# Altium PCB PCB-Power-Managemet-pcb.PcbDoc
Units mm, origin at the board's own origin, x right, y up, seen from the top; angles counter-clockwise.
Board outline 99.48 x 99.65 mm, 2 copper layers (Top Layer, Bottom Layer), stack 1.41 mm thick; 27 components, 20 nets, 70 pads, 5 vias.
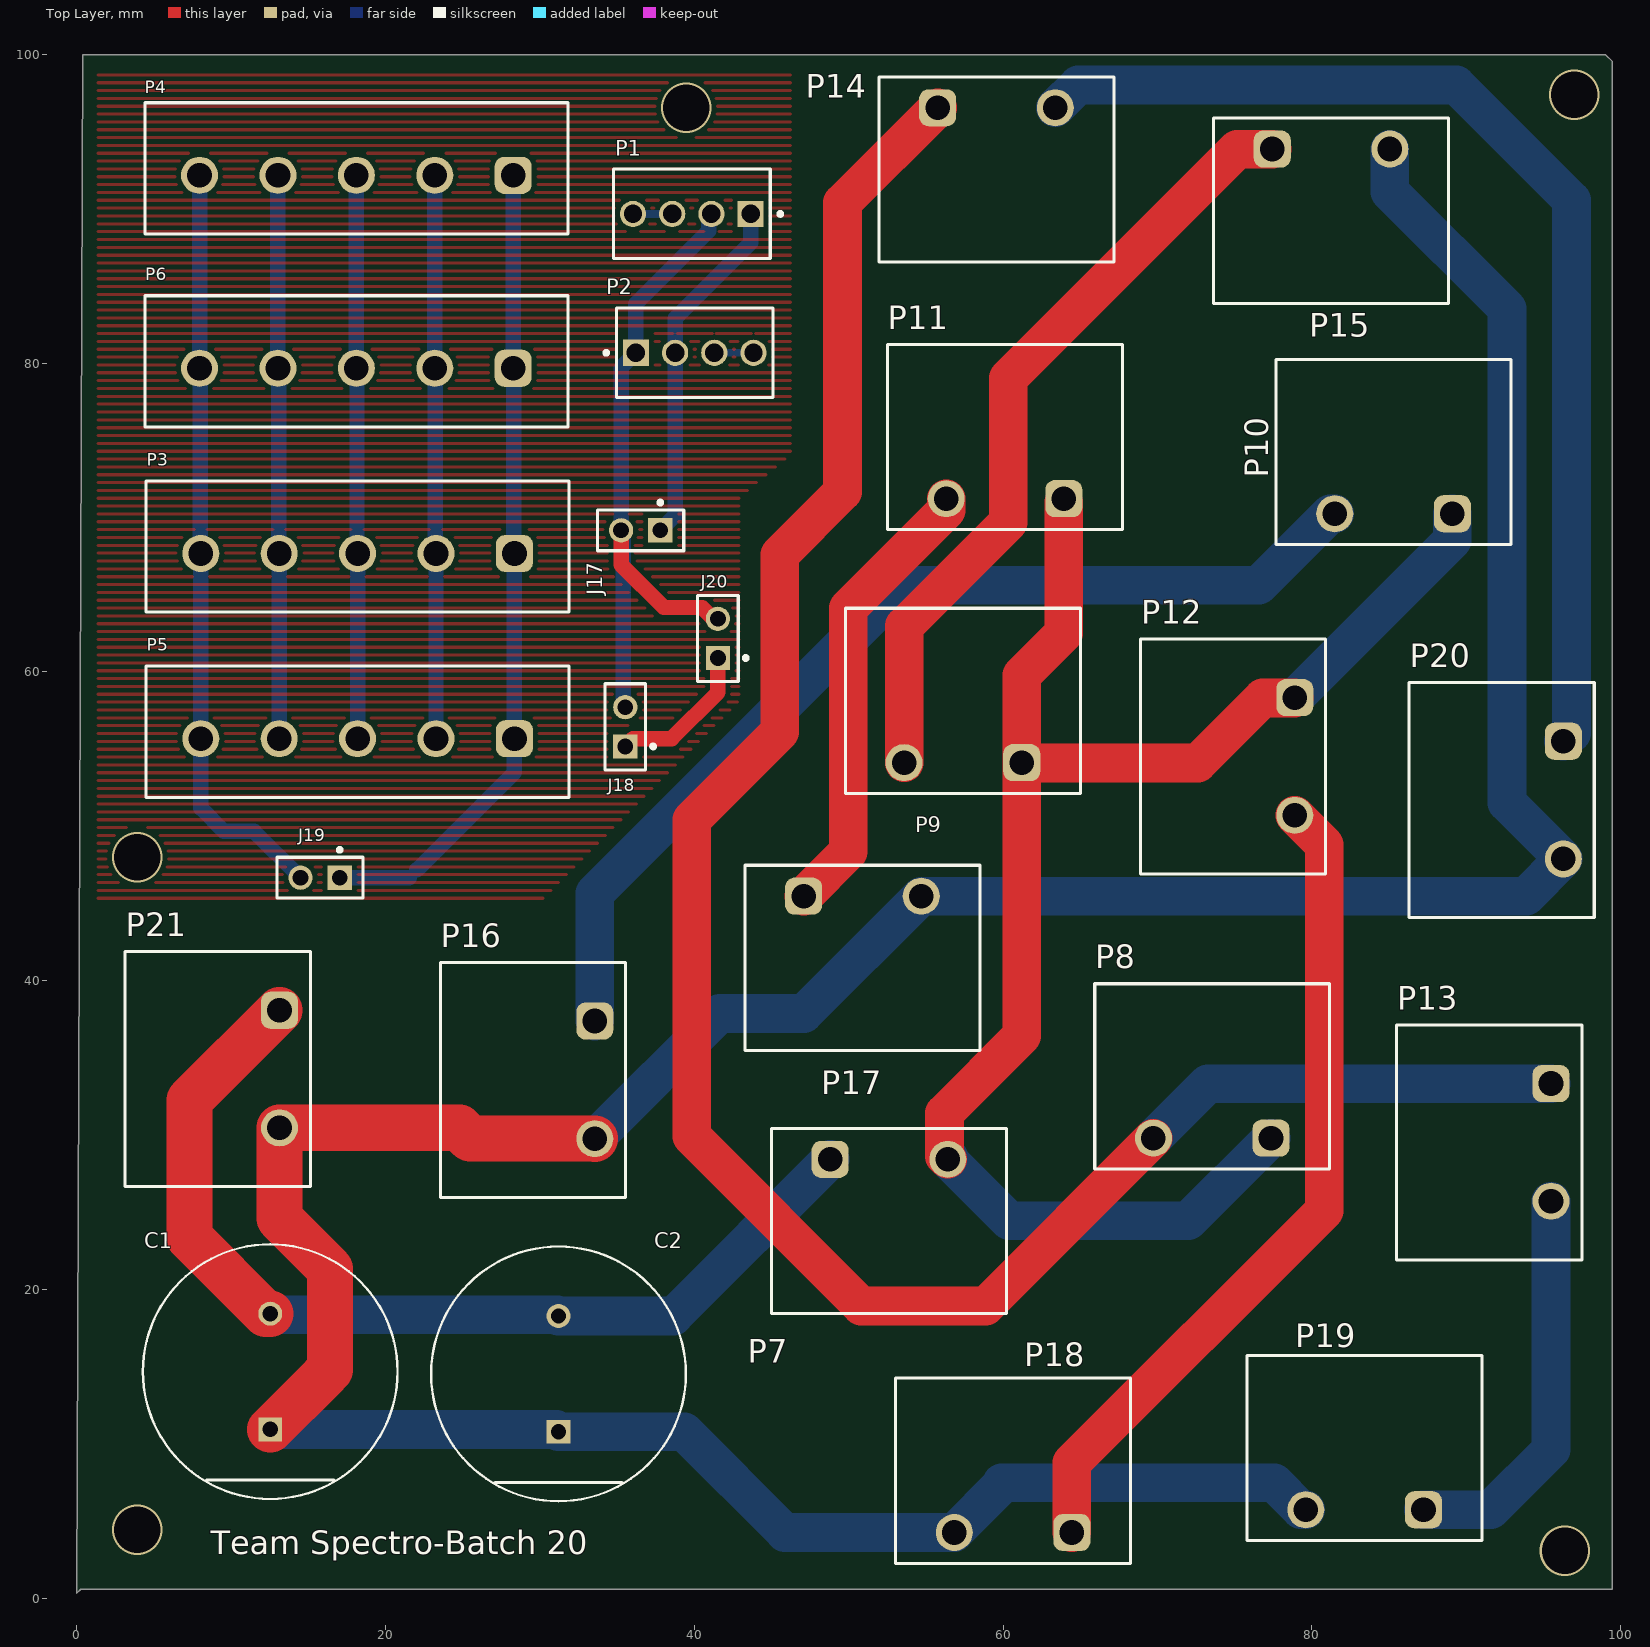
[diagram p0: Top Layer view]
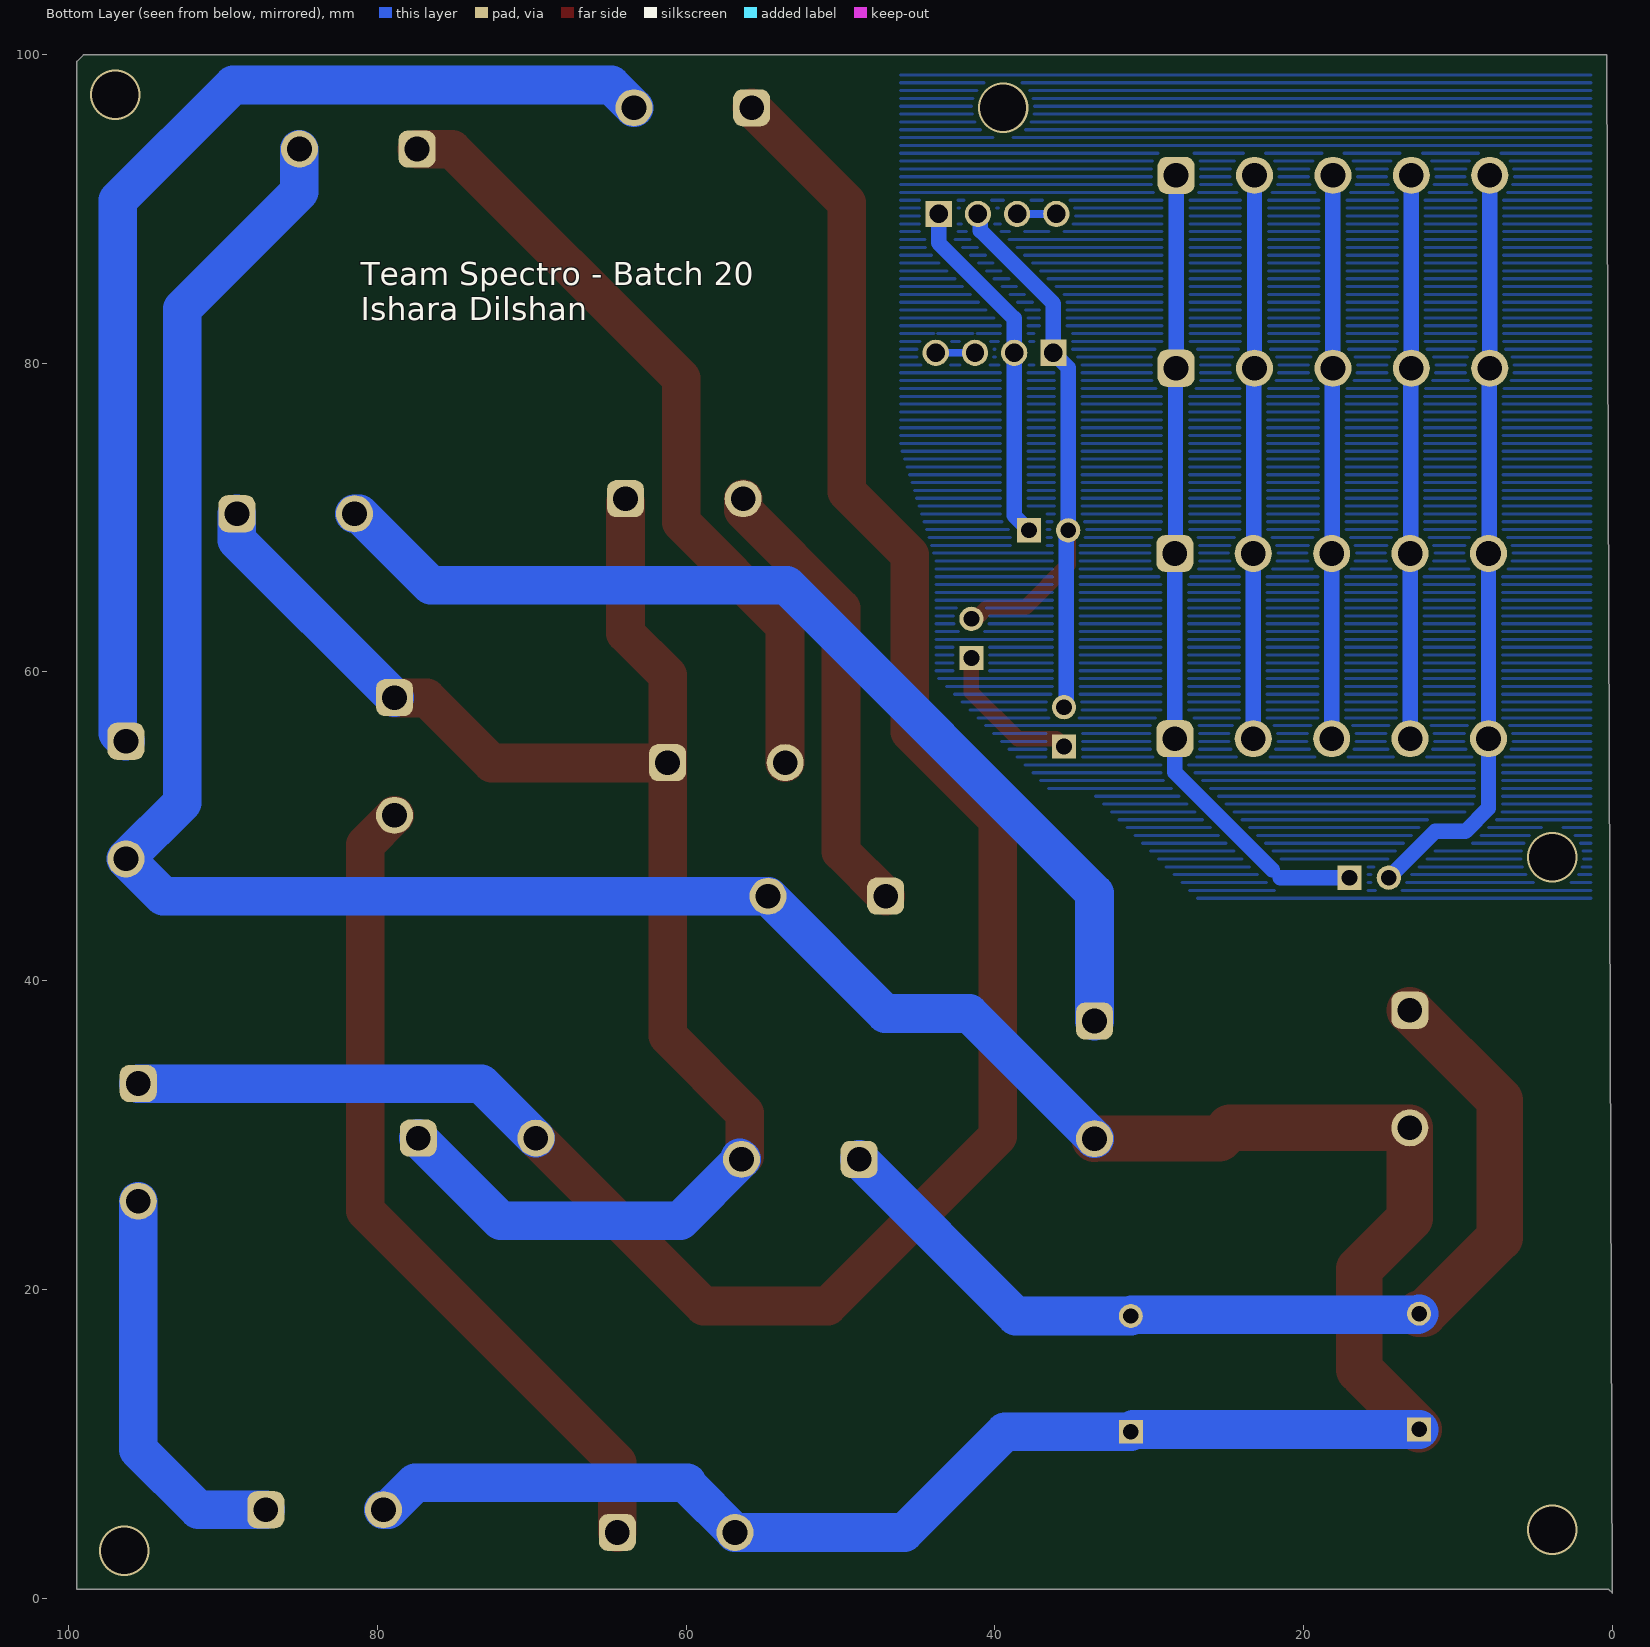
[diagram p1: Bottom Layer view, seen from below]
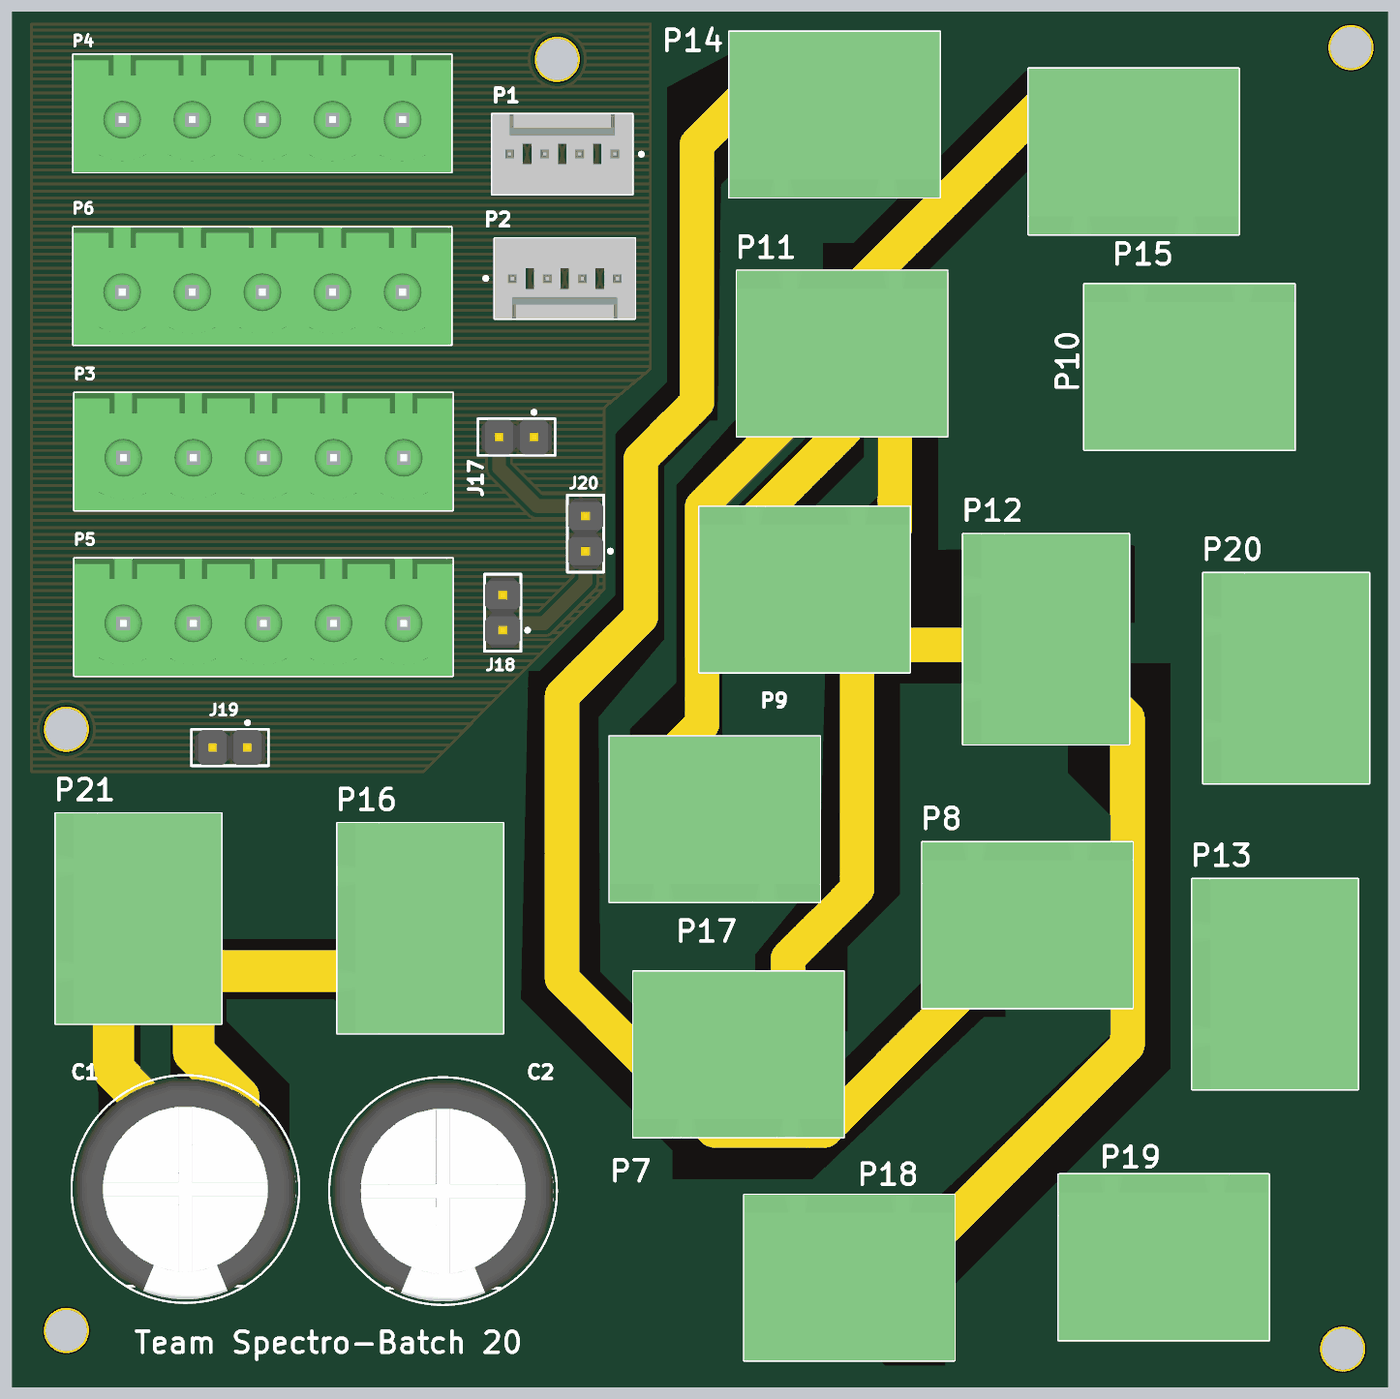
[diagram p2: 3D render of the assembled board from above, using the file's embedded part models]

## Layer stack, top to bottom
Top Solder: solder mask 0.0502, Solder Resist, Dk 3.5
Top Layer: signal copper 0.105
Dielectric 1: dielectric 1.2, FR-4, Dk 4.8
Bottom Layer: signal copper 0.105
Bottom Solder: solder mask 0.0502, Solder Resist, Dk 3.5

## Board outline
0,0.325 0.25,0.575 99.475,0.575 99.475,99.55 99.05,99.975 0.375,99.975

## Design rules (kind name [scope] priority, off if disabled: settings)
Clearance [All] p1: gap=0.3 ignorepadtopadclearanceinfootprint=FALSE
PolygonConnect [All] p1: connectstyle=Relief reliefconductorwidth=0.254 reliefentries=4 polygonreliefangle="90 Angle" airgapwidth=0.254
RoutingVias [All] p1: holewidth=1 width=1.2 viastyle="Through Hole" minholewidth=1 minwidth=1.2 maxholewidth=1 maxwidth=1.2
SilkToSolderMaskClearance [IsPad] p1: minsilkscreentomaskgap=0.2 clearancetoexposedcopper=TRUE
SolderMaskExpansion [All] p1: expansion=0.102 istentingtop=FALSE
Width [All] p1: maxlimit=3 minlimit=0.1 preferedwidth=2 bottomlayer_prefwidth=1 minimp=50.000000 maximp=50.000000 favimp=50.000000
29 further rules are at their usual default settings.

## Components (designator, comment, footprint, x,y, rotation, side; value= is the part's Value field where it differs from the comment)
C1 "cap01" FP-RAD-TH-D_16_0_5-L_25_2-MFG 12.525,14.675 r90 top
C2 "cap02" FP-RAD-TH-D_16_0_5-L_25_2-MFG 31.2,14.525 r90 top
J17 "Vcc" FP-M20-9990245-MFG 36.525,69.175 r180 top
J18 "Rel2" FP-M20-9990245-MFG 35.525,56.445 r90 top
J19 "VoltageSensor" FP-M20-9990245-MFG 15.755,46.675 r180 top
J20 "VoltageSensor" FP-M20-9990245-MFG 41.525,62.175 r90 top
P1 "Rel01" MOLX-22-27-2041_V 39.835,89.675 r0 top
P2 "VoltageSensor" MOLX-22-27-2041_V 40.025,80.675 r180 top
P3 "BMS" 691311500105 18.185,68.125 r180 top
P4 "battery" 691311500105 18.105,92.625 r180 top
P5 "beeper" 691311500105 18.185,56.125 r180 top
P6 "ex" 691311500105 18.105,80.125 r180 top
P7 "MainSwitch" 691313410002 52.61,24.425 r0 top
P8 "SubSwitch" 691313410002 73.55,33.8 r180 top
P9 "SW1" 691313410002 57.4,58.125 r180 top
P10 "SW3" 691313410002 85.3,74.25 r180 top
P11 "SW5" 691313410002 60.125,75.225 r180 top
P12 "SW7" 691313410002 74.9,54.525 r270 top
P13 "SW11" 691313410002 91.5,29.525 r270 top
P14 "SW13" 691313410002 59.575,92.55 r0 top
P15 "SW2" 691313410002 81.25,89.875 r0 top
P16 "SW4" 691313410002 29.55,33.575 r270 top
P17 "SW6" 691313410002 50.89,41.475 r0 top
P18 "SW8" 691313410002 60.65,8.25 r180 top
P19 "SW12" 691313410002 83.425,9.725 r180 top
P20 "SW14" 691313410002 92.3,51.7 r270 top
P21 "PowerIN" 691313410002 9.125,34.275 r270 top

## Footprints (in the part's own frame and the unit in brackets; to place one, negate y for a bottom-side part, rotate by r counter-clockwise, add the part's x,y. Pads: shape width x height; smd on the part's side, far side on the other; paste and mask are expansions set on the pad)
691311500105 [mm] "5,08mm - PCB Headers - Vertical - Closed ends -05p"
  rrect50% 2.4x2.4 hole 1.6: 1(-10.16,0.45)
  round 2.4 hole 1.6: 2(-5.08,0.45) 3(0,0.45) 4(5.08,0.45) 5(10.16,0.45)
  silkscreen extent -13.7,-4.25 13.7,4.25, body extent -13.7,-4.25 13.7,4.25, height 12.05
691313410002 [mm] "7.62 mm - Closed Horizonal PCB Header - 2p"
  rrect50% 2.4x2.4 hole 1.6: 1(-3.81,4)
  round 2.4 hole 1.6: 2(3.81,4)
  silkscreen extent -7.61,-6 7.61,6, body extent -7.62,-6 7.62,6, height 8.55
FP-M20-9990245-MFG [mm]
  rect 1.57x1.57 hole 1.02 paste-1000 mask+0: 1(-1.27,0)
  round 1.57 hole 1.02 paste-1000 mask+0: 2(1.27,0)
  silkscreen extent -2.79,-1.92 2.79,1.32, body extent -2.89,-1.42 2.89,1.42, height 0.25
FP-RAD-TH-D_16_0_5-L_25_2-MFG [mm]
  rect 1.55x1.55 hole 1 paste-1000 mask+0: 1(-3.75,0)
  round 1.55 hole 1 paste-1000 mask+0: 2(3.75,0)
  silkscreen extent -8.25,-8.25 8.25,8.25, body extent -8.35,-8.35 8.35,8.35, height 0.25
MOLX-22-27-2041_V [mm] "CONN, 4-Leads, Body 10.16x5.8mm, Pitch 2.54mm"
  rect 1.7x1.7 hole 1.19: 1(3.81,0)
  round 1.7 hole 1.19: 2(1.27,0) 3(-1.27,0) 4(-3.81,0)
  silkscreen extent -5.08,-2.9 5.86,2.9, body extent -5.08,-2.9 5.08,2.9, height 11.7

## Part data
C1 C2: library part CMP-05427-000445-1, "Aluminum Electrolytic Capacitors (Radial Lead Type) 4700uF ±20% 16V", Capacitance=4.7mF, Case/Package=Radial, ESR (Equivalent Series Resistance)=14mR, Max Operating Temperature=105°C, Min Operating Temperature=-40°C, Package Quantity=100, Ripple Current=3.82A, Tolerance=20%, Voltage=16V
J17 J18 J19 J20: library part CMP-15831-000105-1, "CONN HEADER VERT 2POS 2.54MM", Case/Package=SIL, Color=Black, Contact Resistance=25mR, Current=3A, Flammability Rating="UL94 V-0", Insulation Resistance=10GR, Max Operating Temperature=105°C, Min Operating Temperature=-40°C, Package Quantity=1000, Voltage=50V, Voltage Rating (AC)=750V
P1 P2: library part CMP-2000-05243-1, "Male Header, Pitch 2.54 mm, 1 x 4 Position, Height 11.7 mm, Tail Length 3.56 mm, RoHS, Bulk", Current Rating=4A, Manufacturer=Molex, Operating Temperature=0degCto+75degC, Voltage Rating=250V
P3 P4 P5 P6: library part CMP-1502-02149-2, Color=Green, Current=20A, Voltage=300V
P7 P8 P9 P10 P11 P12 P13 P14 P15 P16 P17 P18 P19 P20 P21: library part CMP-1502-02424-2, Color=Green, Current=20A, Voltage=300V

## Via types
v1: diameter 3.27, hole 3, Top Layer to Bottom Layer, 5 vias

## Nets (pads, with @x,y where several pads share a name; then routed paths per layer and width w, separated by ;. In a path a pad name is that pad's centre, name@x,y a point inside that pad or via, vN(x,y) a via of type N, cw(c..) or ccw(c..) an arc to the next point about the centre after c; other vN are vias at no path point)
5V: J17.1 P1.1 P2.2 | length 22.9
  Bottom Layer w1: J17.1 38.755,70.135 P2.2 38.755,82.905 43.645,87.795 P1.1
B+: J19.1 P3.1 P4.1 P5.1 P6.1 | length 52.9
  Bottom Layer w0.381: 21.525,46.675 22.025,47.175
  Bottom Layer w1: J19.1 21.525,46.675 ; 22.025,47.175 28.345,53.495 P3.1 28.305,67.715 28.305,79.635 P6.1 P4.1
B-: J19.2 P3.5 P4.5 P5.5 P6.5 | length 49.4
  Bottom Layer w1: P4.5 P6.5 7.985,79.635 7.985,67.715 P3.5 P5.5 8.025,51.175 9.525,49.675 11.485,49.675 J19.2
C1+: P3.4 P4.4 P5.4 P6.4 | length 36.5
  Bottom Layer w0.3: P6.4 P6.4@13.065,79.635 ; P3.4@13.065,67.715 P3.4 ; P5.4@13.094,55.686 P5.4
  Bottom Layer w1: P6.4 P4.4 ; P3.4@13.065,67.715 P6.4@13.065,79.635 ; P5.4 P3.4
C2+: P3.3 P4.3 P5.3 P6.3 | length 36.5
  Bottom Layer w1: P4.3@18.097,92.167 P4.3 P6.3 18.145,79.635 18.145,67.715 P3.3 P5.3
C3+: P3.2 P4.2 P5.2 P6.2 | length 36.5
  Bottom Layer w1: P4.2 P6.2 23.225,79.635 23.225,67.715 P3.2 P5.2
GND: J17.2 J18.2 J20.2 P1.2 P2.1 | length 44.4
  Top Layer w1: J17.2 35.255,66.945 38.025,64.175 40.508,64.175 41.239,63.445 J20.2
  Bottom Layer w1: J18.2 35.39,57.85 35.39,69.04 J17.2 35.255,79.715 P2.1 36.215,83.865 40.946,88.596 40.946,89.516 P1.2
NetC1_1: C1.1 C2.1 P15.2 P16.2 P17.2 P18.2 P19.2 P20.2 P21.2 | length 236.1
  Top Layer w3: C1.1 16,14.4 16.4,14.8 16.4,21.325 13.125,24.6 P21.2 24.785,30.465 25.475,29.775 33.54,29.775 P16.2
  Bottom Layer w2.5: C1.1 31.05,10.925 C2.1 39.35,10.775 45.875,4.25 P18.2 59.925,7.335 59.925,7.463 77.562,7.463 79.3,5.725 P19.2 ; P16.2 41.66,37.875 47.1,37.875 P17.2 93.885,45.475 P20.2 92.65,51.54 92.65,83.525 85.06,91.115 P15.2
NetC1_2: C1.2 C2.2 P7.1 P21.1 | length 65
  Top Layer w3: C1.2 12.225,18.425 7.3,23.35 7.3,32.26 P21.1
  Bottom Layer w2.5: C1.2 12.6,18.35 31.125,18.35 C2.2 38.65,18.275 P7.1
NetP7_2: P7.2 P8.1 P9.1 P10.1 P11.1 P12.1 | length 106.3
  Top Layer w2.5: P7.2 56.205,28.64 56.205,31.421 61.21,36.426 61.21,59.776 63.935,62.501 P11.1@63.935,70.986 ; P9.1@61.234,54.101 72.61,54.101 76.82,58.311 P12.1@78.876,58.311
  Bottom Layer w2.5: P7.2@56.521,28.527 P7.2 60.395,24.45 72.01,24.45 P8.1 ; P12.1 89.11,68.545 P10.1
NetP8_2: P8.2 P13.1 P14.1 | length 139.4
  Top Layer w2.5: P14.1 49.6,90.385 49.6,71.675 45.525,67.6 45.525,56.125 39.825,50.425 39.825,29.925 50.825,18.925 58.865,18.925 P8.2
  Bottom Layer w2.5: P8.2 73.275,33.335 P13.1
NetP9_2: P9.2 P15.1 | length 51
  Top Layer w2.5: P9.2@53.6,54.125 53.6,62.975 60.325,69.7 60.325,79.025 75.175,93.875 P15.1
NetP10_2: P10.2 P16.1 | length 66.4
  Bottom Layer w2.5: P16.1 33.55,45.677 53.49,65.617 76.555,65.617 81.188,70.25 P10.2
NetP11_2: P11.2 P17.1 | length 29.6
  Top Layer w2.5: P17.1 49.975,48.37 49.975,64.125 56.315,70.465 P11.2
NetP12_2: P12.2 P18.1 | length 54
  Top Layer w2.5: P18.1 64.46,8.76 80.8,25.1 80.8,48.815 P12.2
NetP13_2: P13.2 P19.1 | length 26
  Bottom Layer w2.5: P19.1 91.6,5.725 95.5,9.625 P13.2
NetP14_2: P14.2 P20.1 | length 72.4
  Bottom Layer w2.5: P14.2 64.86,98.025 89.35,98.025 96.825,90.55 96.825,56.035 P20.1
Rel2-Signal: J18.1 J20.1 | length 9.7
  Top Layer w1: J18.1 36.025,55.675 38.525,55.675 41.525,58.675 J20.1
S1: P1.3 P1.4 | length 2.5
  Bottom Layer w0.5: P1.4 P1.3
S2: P2.3 P2.4 | length 2.5
  Bottom Layer w0.5: P2.3 P2.4
copper on no net:
  other v1: 96.4,3.075 3.9,4.425 3.9,48 39.475,96.55 97,97.4

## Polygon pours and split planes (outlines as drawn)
NetP12_2 on Top Solder "NONET_L-01_P-001" (solid): 61.875,3.675 61.875,3.25 63.25,1.875 67.6,1.875 67.6,7.075 83.925,23.4 83.925,52.8 78.025,52.8 76.475,51.25 76.475,44.85 79.575,41.75 79.575,25.875 79.025,25.325 61.7,9.05
NetP7_2 on Top Solder "NONET_L-01_P-001" (solid): 62.725,72.8 62.725,64.9 59.15,61.325 58.475,37.35 53.825,31.675 53.825,26.5 54.3,26.025 54.375,26.1 60.525,26.1 60.525,32.25 64.325,36.05 64.325,51.3 74.075,51.3 78.475,55.7 81.325,55.7 81.325,61.3 81.275,61.35 79.525,61.3 67.1,61 67.1,72.75
NetP9_2 on Top Solder "NONET_L-01_P-001" (solid): 52.425,52.525 52.275,52.675 52.425,64.05 52.525,64.15 58.725,70.35 58.725,83.25 60.975,83.25 73.3,95.575 73.425,95.7 79.15,95.475 79.15,92.575 77.95,91.375 76.45,90.925 75.875,90.75 61.7,76.575 61.7,67.725 55.4,61.425 55.4,52.7
NetP11_2 on Top Solder "NONET_L-01_P-001" (solid): 54.363,72.625 57.75,72.625 57.95,72.625 57.95,70.525 51.45,64.025 51.45,46.8 47.15,42.5 44.75,42.5 44.75,48 48.1,51.35 48.1,65.725 48.675,66.3
NetP8_2 on Top Solder "NONET_L-01_P-001" (solid): 54.075,98.05 57.475,98.05 57.475,97.95 57.475,97.8 57.475,92.3 56.15,92.3 51.35,87.5 51.1,70.375 50.55,70.375 47.225,67.05 47.225,54.512 42.475,48.875 42.475,48.675 42.6,30.425 42.625,30.4 50.7,22.325 58.55,22.325 68.075,31.85 70.8,31.85 71.875,30.65 71.975,30.425 71.975,27.15 70.4,27.15 58,15.4 57.35,15.4 47.825,15.4 47.825,17.475 36.85,28.45 36.85,28.725 37.375,52.225 38.175,52.225 43.675,57.725 43.675,69.325 43.825,69.575 47.425,73.175 47.425,73.5 47.425,94.525
NetC1_1 on Top Solder "NONET_L-01_P-001" (solid): 11.275,11.675 11.275,9.95 11.275,9.775 12,9.775 16.35,9.775 16.35,10.05 20.075,14.1 20.075,14.475 20.075,22.275 15.525,26.825 15.525,28.45 23.25,28.45 25.05,26.65 34.95,26.65 34.95,32.525 34.675,32.8 13.075,32.8 11.45,30.9 11.45,30.625 11.45,22.925 11.725,22.925 14.9,19.75 14.9,15.575
NetC1_2 on Top Solder "NONET_L-01_P-001" (solid): 11.275,39.175 11.55,39.45 14.5,39.45 14.5,36.45 9.25,31.2 9.25,23.4 12.9,19.75 13.525,19.75 13.525,16.2 13.45,16.275 6.225,16.275 6.225,21.6 5.825,23.9 5.825,28.25 5.825,35.625
NetP8_2 on Bottom Solder "NONET_L-01_P-001" (solid): 67.325,35.85 67.25,28.625 70.65,28.625 74.15,32.125 82.6,32.125 84.7,30.025 98.3,30.025 98.3,35.525
NetP7_2 on Bottom Solder "NONET_L-01_P-001" (solid): 54.175,30.025 60.025,30.025 63.275,26.775 71.425,26.775 76.025,31.375 79.175,31.375 79.175,26.95 73.675,21.45 58.45,21.45 54.25,25.65
NetP14_2 on Bottom Solder "NONET_L-01_P-001" (solid): 61.4,94.85 61.5,94.75 61.6,94.85 70.975,94.85 72.775,96.65 88.675,96.65 88.675,95.55 95.357,88.868 95.044,54.275 98.725,54.275 98.825,54.375 98.825,93.575 97.075,93.575 91.1,99.55 61.4,99.55
NetP7_2 on Bottom Solder "NONET_L-01_P-001" (solid): 77.2,59.925 77.2,56.125 77.525,56.125 77.875,56.125 82.25,56.125 82.25,59.325 90.425,67.5 90.425,72.975 87.625,72.975 86.3,71.65 86.3,68.745
NetP10_2 on Bottom Solder "NONET_L-01_P-001" (solid): 36.075,40.075 36.075,37.502 34.673,36.1 33.15,36.1 30.85,36.1 30.85,47.225 34.9,51.275 36.5,51.275 53.6,68.375 53.85,68.125 76.375,68.125 80.75,72.5 83.85,72.5 83.85,68.675 77.775,62.6 67.7,62.6 67.375,62.925 67.275,62.825 55,62.825
NetC1_1 on Bottom Solder "NONET_L-01_P-001" (solid): 31.425,31.98 31.425,26.075 36.125,26.075 46.025,35.975 52.25,35.975 52.25,37.625 57.575,42.95 98.5,42.95 98.5,49.675 95.025,53.15 94.1,53.15 94.1,85.85 87.4,92.55 87.4,95.9 83,95.9 82.075,94.975 82.075,88.775 91.225,79.625 91.225,48.6 84.2,48.6 84.05,48.45 83.9,48.6 54.25,48.6 45.575,39.925 41.947,39.925
NetP13_2 on Bottom Solder "NONET_L-01_P-001" (solid): 93.075,28.225 93.25,28.225 97.975,28.225 97.975,8.4 92.825,3.25 84.95,3.25 84.95,7.975 84.95,8.6 85.175,8.6 90.825,8.6 90.825,10.175 92.825,12.175
NetC1_1 on Bottom Solder "NONET_L-01_P-001" (solid): 9.925,13.75 9.925,6.35 39.425,6.35 44.35,1.425 44.4,1.475 59.325,1.475 59.325,3.4 62.275,6.35 73.7,6.35 78.3,2.1 78.7,2.1 82.825,2.1 82.825,9.7 81.664,10.861
NetC1_2 on Bottom Solder "NONET_L-01_P-001" (solid): 9.937,21.638 9.937,16.075 40.925,16.075 51.9,27.05 51.9,31.55 46.05,31.55 36.6,22.1
no net on Bottom Layer "NONET_L02_P005" (hatched Horizontal grid 0.508 track 0.203, pour order 5): 43.8,67.175 43.8,59.725 36.225,52.15 33.675,52.15 26.6,45.075 1.375,45.075 1.375,99.05 46.025,99.05 46.125,98.95 46.125,74.675
no net on Top Layer "NONET_L01_P006" (hatched Horizontal grid 0.508 track 0.203, pour order 6): 42.875,71.3 42.875,58.225 42.875,58.125 29.775,44.925 1.375,44.925 1.375,44.975 1.375,45.075 1.375,99.1 46.225,99.1 46.225,99 46.225,98.9 46.225,74.1

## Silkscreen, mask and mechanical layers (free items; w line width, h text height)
Top Overlay:
  text "Team Spectro-Batch 20" at 8.679,2.837 h1.52
Bottom Overlay:
  text "Team Spectro - Batch 20 / Ishara Dilshan" at 81.1,82.8 h1.5
Board:
  lines w0.2: 0.325,0.575 99.55,0.575 99.575,0.6 99.575,99.9 0.325,99.9 0.325,0.575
